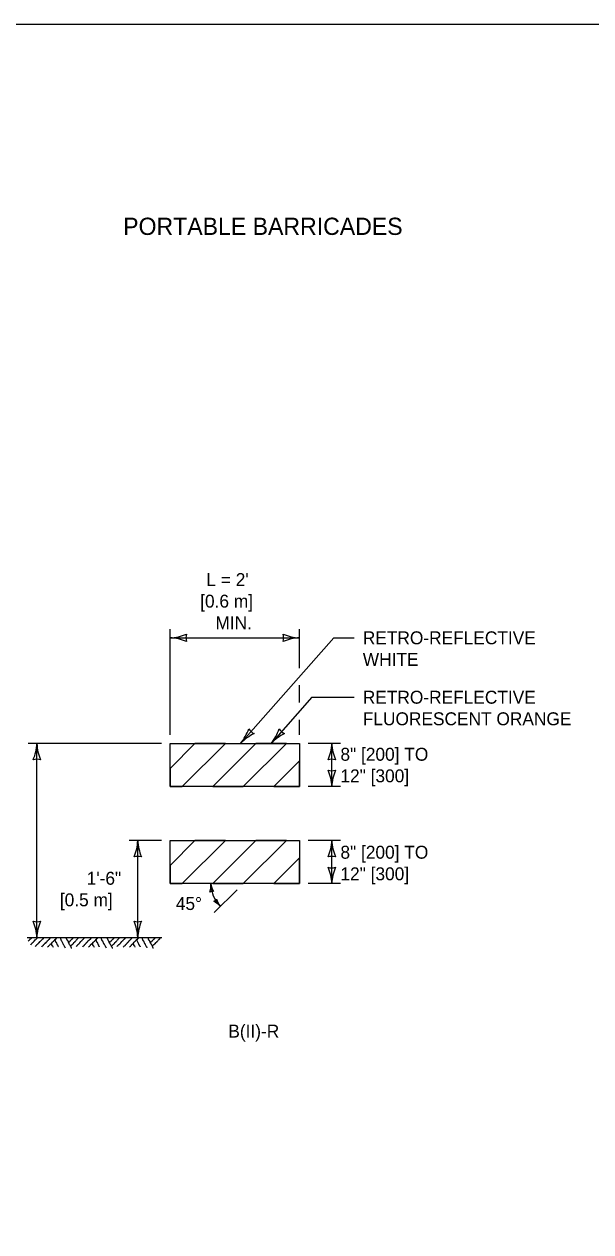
# Model space of a CAD drawing. Extents: x 49991.4 to 50021, y 49987.6 to 50011.4.
# Drawn here: x 50002.59 to 50005.22, y 49993.4 to 49999 of the extents above; entities that cross this region are included whole.
import ezdxf

# ---------------------------------------------------------------- set-up
doc = ezdxf.new("R2010")
doc.units = 0
for name, color, linetype in [('Level 1', 7, 'Continuous'), ('Level 2', 7, 'Continuous'), ('Level 3', 7, 'Continuous')]:
    doc.layers.add(name, color=color, linetype=linetype)

msp = doc.modelspace()

# ---------------------------------------------------------------- linework, layer by layer
at = {"layer": 'Level 1'}
for p, q in [((50003.2643, 49995.5483), (50003.3794, 49995.6636)), ((50003.3794, 49995.6636), (50003.2643, 49995.5483)), ((50003.321, 49995.4636), (50003.5207, 49995.6636)), ((50003.321, 49995.4636), (50003.5207, 49995.6636)), ((50003.4623, 49995.4636), (50003.662, 49995.6636)), ((50003.662, 49995.6636), (50003.4623, 49995.4636)), ((50003.6037, 49995.4636), (50003.8034, 49995.6636)), ((50003.6037, 49995.4636), (50003.8034, 49995.6636)), ((50003.7449, 49995.4636), (50003.8643, 49995.5832)), ((50003.8643, 49995.5832), (50003.7449, 49995.4636)), ((50003.2643, 49995.0983), (50003.3794, 49995.2136)), ((50003.3794, 49995.2136), (50003.2643, 49995.0983)), ((50003.321, 49995.0136), (50003.5207, 49995.2136)), ((50003.321, 49995.0136), (50003.5207, 49995.2136)), ((50003.4623, 49995.0136), (50003.662, 49995.2136)), ((50003.662, 49995.2136), (50003.4623, 49995.0136)), ((50003.6037, 49995.0136), (50003.8034, 49995.2136)), ((50003.6037, 49995.0136), (50003.8034, 49995.2136)), ((50003.7449, 49995.0136), (50003.8643, 49995.1332)), ((50003.8643, 49995.1332), (50003.7449, 49995.0136))]:
    msp.add_line(p, q, dxfattribs=at)
for points in [[(49999.3835, 49998.9992), (50016.7501, 49998.9992), (50016.7501, 49987.7988), (49999.3835, 49987.7988)], [(50003.2643, 49995.6636), (50003.8643, 49995.6636), (50003.8643, 49995.4636), (50003.2643, 49995.4636)], [(50003.2643, 49995.2136), (50003.8643, 49995.2136), (50003.8643, 49995.0136), (50003.2643, 49995.0136)]]:
    msp.add_lwpolyline(points, close=True, dxfattribs=at)
for points in [[(50003.5207, 49995.6636), (50003.3794, 49995.6636)], [(50003.8034, 49995.6636), (50003.662, 49995.6636)], [(50003.7449, 49995.4636), (50003.8643, 49995.4636), (50003.8643, 49995.5832)], [(50003.2643, 49995.5483), (50003.2643, 49995.4636)], [(50003.2643, 49995.4636), (50003.321, 49995.4636)], [(50003.4623, 49995.4636), (50003.6037, 49995.4636)], [(50003.5207, 49995.2136), (50003.3794, 49995.2136)], [(50003.8034, 49995.2136), (50003.662, 49995.2136)], [(50003.7449, 49995.0136), (50003.8643, 49995.0136), (50003.8643, 49995.1332)], [(50003.2643, 49995.0983), (50003.2643, 49995.0136)], [(50003.2643, 49995.0136), (50003.321, 49995.0136)], [(50003.4623, 49995.0136), (50003.6037, 49995.0136)], [(50002.6211, 49994.7636), (50002.6209, 49994.761), (50002.6177, 49994.7583), (50002.6176, 49994.7568), (50002.6161, 49994.757), (50002.6144, 49994.7542), (50002.613, 49994.7543), (50002.6128, 49994.7528), (50002.6097, 49994.7502), (50002.6096, 49994.7488), (50002.6081, 49994.7489), (50002.6065, 49994.7462)], [(50002.6513, 49994.7636), (50002.6424, 49994.7562), (50002.6423, 49994.7547), (50002.6409, 49994.7548), (50002.6392, 49994.7521), (50002.6362, 49994.7508), (50002.6343, 49994.7467), (50002.6313, 49994.7454), (50002.6312, 49994.744), (50002.628, 49994.7413), (50002.6279, 49994.7398), (50002.6264, 49994.7399), (50002.6247, 49994.7372), (50002.6233, 49994.7373), (50002.6231, 49994.7359), (50002.62, 49994.7332), (50002.6199, 49994.7317), (50002.6184, 49994.7319), (50002.6167, 49994.729)], [(50002.6784, 49994.7636), (50002.6722, 49994.7566), (50002.6721, 49994.7551), (50002.6706, 49994.7552), (50002.6689, 49994.7524), (50002.6642, 49994.7484), (50002.664, 49994.747), (50002.6625, 49994.7472), (50002.6608, 49994.7444), (50002.6579, 49994.7431), (50002.656, 49994.7389), (50002.653, 49994.7376), (50002.6529, 49994.7362), (50002.6496, 49994.7336), (50002.6495, 49994.7321), (50002.6481, 49994.7322), (50002.6464, 49994.7295), (50002.645, 49994.7296), (50002.6448, 49994.7281), (50002.6417, 49994.7255), (50002.6416, 49994.724), (50002.6401, 49994.7241), (50002.6383, 49994.7213)], [(50002.7099, 49994.7636), (50002.7017, 49994.7544), (50002.7016, 49994.7529), (50002.7001, 49994.7531), (50002.6983, 49994.7503), (50002.6937, 49994.7463), (50002.6936, 49994.7449), (50002.6921, 49994.745), (50002.6904, 49994.7421), (50002.6873, 49994.741), (50002.6855, 49994.7367), (50002.6825, 49994.7355), (50002.6824, 49994.7341), (50002.6792, 49994.7315), (50002.679, 49994.73), (50002.6776, 49994.7301), (50002.6759, 49994.7273), (50002.6744, 49994.7275), (50002.6743, 49994.726), (50002.6711, 49994.7233), (50002.671, 49994.7218), (50002.6696, 49994.722), (50002.6679, 49994.7192)], [(50002.7386, 49994.7636), (50002.7299, 49994.7538), (50002.7297, 49994.7524), (50002.7282, 49994.7525), (50002.7266, 49994.7497), (50002.7218, 49994.7457), (50002.7217, 49994.7443), (50002.7202, 49994.7444), (50002.7186, 49994.7416), (50002.7156, 49994.7404), (50002.7137, 49994.7361), (50002.7106, 49994.7349), (50002.7105, 49994.7335), (50002.7073, 49994.7309), (50002.7072, 49994.7294), (50002.7058, 49994.7295), (50002.704, 49994.7267), (50002.7027, 49994.7268), (50002.7025, 49994.7254), (50002.6993, 49994.7227), (50002.6992, 49994.7213), (50002.6978, 49994.7214), (50002.696, 49994.7186)], [(50002.713, 49994.7376), (50002.7165, 49994.7271), (50002.7194, 49994.7254), (50002.7218, 49994.7194)], [(50002.7295, 49994.7538), (50002.733, 49994.7433), (50002.7357, 49994.7416), (50002.7406, 49994.7294), (50002.742, 49994.7293), (50002.7433, 49994.7263), (50002.7431, 49994.7248), (50002.7458, 49994.7216), (50002.7461, 49994.7209)], [(50002.754, 49994.7636), (50002.7586, 49994.7502), (50002.7613, 49994.7485), (50002.7661, 49994.7363), (50002.7676, 49994.7362), (50002.7687, 49994.7333), (50002.7686, 49994.7318), (50002.7713, 49994.7287), (50002.7736, 49994.7226), (50002.7751, 49994.7224), (50002.7777, 49994.7161)], [(50002.7815, 49994.7636), (50002.7851, 49994.7527), (50002.7878, 49994.751), (50002.7927, 49994.7389), (50002.7942, 49994.7388), (50002.7954, 49994.7357), (50002.7952, 49994.7342), (50002.7979, 49994.7311), (50002.8004, 49994.725), (50002.8017, 49994.7249), (50002.8054, 49994.7158), (50002.8083, 49994.7156)], [(50002.8155, 49994.7636), (50002.8093, 49994.7565), (50002.8092, 49994.755), (50002.8077, 49994.7552), (50002.806, 49994.7524), (50002.8012, 49994.7484), (50002.801, 49994.747), (50002.7996, 49994.7471), (50002.7979, 49994.7443), (50002.7949, 49994.7431), (50002.7942, 49994.7415)], [(50002.841, 49994.7636), (50002.8309, 49994.7525), (50002.8308, 49994.751), (50002.8293, 49994.7511), (50002.8277, 49994.7483), (50002.8229, 49994.7444), (50002.8228, 49994.7429), (50002.8213, 49994.7431), (50002.8196, 49994.7403), (50002.8166, 49994.739), (50002.8147, 49994.7348), (50002.8116, 49994.7336), (50002.8115, 49994.7321), (50002.8084, 49994.7294), (50002.8082, 49994.728), (50002.8068, 49994.7281), (50002.8051, 49994.7254), (50002.8037, 49994.7255), (50002.8037, 49994.7251)], [(50002.8681, 49994.7636), (50002.8619, 49994.7566), (50002.8618, 49994.7551), (50002.8603, 49994.7552), (50002.8586, 49994.7524), (50002.8539, 49994.7484), (50002.8537, 49994.747), (50002.8522, 49994.7472), (50002.8505, 49994.7444), (50002.8476, 49994.7431), (50002.8457, 49994.7389), (50002.8427, 49994.7376), (50002.8426, 49994.7362), (50002.8393, 49994.7336), (50002.8392, 49994.7321), (50002.8378, 49994.7322), (50002.8361, 49994.7295), (50002.8347, 49994.7296), (50002.8345, 49994.7281), (50002.8314, 49994.7255), (50002.8313, 49994.724), (50002.8298, 49994.7241), (50002.828, 49994.7213)], [(50002.8996, 49994.7636), (50002.8914, 49994.7544), (50002.8913, 49994.7529), (50002.8898, 49994.7531), (50002.888, 49994.7503), (50002.8834, 49994.7463), (50002.8833, 49994.7449), (50002.8818, 49994.745), (50002.8801, 49994.7421), (50002.877, 49994.741), (50002.8752, 49994.7367), (50002.8722, 49994.7355), (50002.8721, 49994.7341), (50002.8689, 49994.7315), (50002.8687, 49994.73), (50002.8673, 49994.7301), (50002.8656, 49994.7273), (50002.8641, 49994.7275), (50002.864, 49994.726), (50002.8608, 49994.7233), (50002.8607, 49994.7218), (50002.8593, 49994.722), (50002.8576, 49994.7192)], [(50002.9283, 49994.7636), (50002.9196, 49994.7538), (50002.9194, 49994.7524), (50002.9179, 49994.7525), (50002.9163, 49994.7497), (50002.9115, 49994.7457), (50002.9114, 49994.7443), (50002.9099, 49994.7444), (50002.9083, 49994.7416), (50002.9053, 49994.7404), (50002.9034, 49994.7361), (50002.9003, 49994.7349), (50002.9002, 49994.7335), (50002.897, 49994.7309), (50002.8969, 49994.7294), (50002.8955, 49994.7295), (50002.8937, 49994.7267), (50002.8924, 49994.7268), (50002.8922, 49994.7254), (50002.889, 49994.7227), (50002.8889, 49994.7213), (50002.8875, 49994.7214), (50002.8857, 49994.7186)], [(50002.9027, 49994.7376), (50002.9062, 49994.7271), (50002.9091, 49994.7254), (50002.9115, 49994.7194)], [(50002.9192, 49994.7538), (50002.9227, 49994.7433), (50002.9254, 49994.7416), (50002.9303, 49994.7294), (50002.9317, 49994.7293), (50002.933, 49994.7263), (50002.9328, 49994.7248), (50002.9355, 49994.7216), (50002.9358, 49994.7209)], [(50002.9437, 49994.7636), (50002.9483, 49994.7502), (50002.951, 49994.7485), (50002.9558, 49994.7363), (50002.9573, 49994.7362), (50002.9584, 49994.7333), (50002.9583, 49994.7318), (50002.961, 49994.7287), (50002.9633, 49994.7226), (50002.9648, 49994.7224), (50002.9674, 49994.7161)], [(50002.9712, 49994.7636), (50002.9748, 49994.7527), (50002.9775, 49994.751), (50002.9824, 49994.7389), (50002.9839, 49994.7388), (50002.9851, 49994.7357), (50002.9849, 49994.7342), (50002.9876, 49994.7311), (50002.9901, 49994.725), (50002.9914, 49994.7249), (50002.9951, 49994.7158), (50002.998, 49994.7156)], [(50003.0052, 49994.7636), (50002.999, 49994.7565), (50002.9989, 49994.755), (50002.9974, 49994.7552), (50002.9957, 49994.7524), (50002.9909, 49994.7484), (50002.9907, 49994.747), (50002.9893, 49994.7471), (50002.9876, 49994.7443), (50002.9846, 49994.7431), (50002.9839, 49994.7415)], [(50003.0307, 49994.7636), (50003.0206, 49994.7525), (50003.0205, 49994.751), (50003.019, 49994.7511), (50003.0174, 49994.7483), (50003.0126, 49994.7444), (50003.0125, 49994.7429), (50003.011, 49994.7431), (50003.0093, 49994.7403), (50003.0063, 49994.739), (50003.0044, 49994.7348), (50003.0013, 49994.7336), (50003.0012, 49994.7321), (50002.9981, 49994.7294), (50002.9979, 49994.728), (50002.9965, 49994.7281), (50002.9948, 49994.7254), (50002.9934, 49994.7255), (50002.9934, 49994.7251)], [(50003.0578, 49994.7636), (50003.0516, 49994.7566), (50003.0515, 49994.7551), (50003.05, 49994.7552), (50003.0483, 49994.7524), (50003.0436, 49994.7484), (50003.0434, 49994.747), (50003.0419, 49994.7472), (50003.0402, 49994.7444), (50003.0373, 49994.7431), (50003.0354, 49994.7389), (50003.0324, 49994.7376), (50003.0323, 49994.7362), (50003.029, 49994.7336), (50003.0289, 49994.7321), (50003.0275, 49994.7322), (50003.0258, 49994.7295), (50003.0244, 49994.7296), (50003.0242, 49994.7281), (50003.0211, 49994.7255), (50003.021, 49994.724), (50003.0195, 49994.7241), (50003.0177, 49994.7213)], [(50003.0893, 49994.7636), (50003.0811, 49994.7544), (50003.081, 49994.7529), (50003.0795, 49994.7531), (50003.0777, 49994.7503), (50003.0731, 49994.7463), (50003.073, 49994.7449), (50003.0715, 49994.745), (50003.0698, 49994.7421), (50003.0667, 49994.741), (50003.0649, 49994.7367), (50003.0619, 49994.7355), (50003.0618, 49994.7341), (50003.0586, 49994.7315), (50003.0584, 49994.73), (50003.057, 49994.7301), (50003.0553, 49994.7273), (50003.0538, 49994.7275), (50003.0537, 49994.726), (50003.0505, 49994.7233), (50003.0504, 49994.7218), (50003.049, 49994.722), (50003.0473, 49994.7192)], [(50003.118, 49994.7636), (50003.1093, 49994.7538), (50003.1091, 49994.7524), (50003.1076, 49994.7525), (50003.106, 49994.7497), (50003.1012, 49994.7457), (50003.1011, 49994.7443), (50003.0996, 49994.7444), (50003.098, 49994.7416), (50003.095, 49994.7404), (50003.0931, 49994.7361), (50003.09, 49994.7349), (50003.0899, 49994.7335), (50003.0867, 49994.7309), (50003.0866, 49994.7294), (50003.0852, 49994.7295), (50003.0834, 49994.7267), (50003.0821, 49994.7268), (50003.0819, 49994.7254), (50003.0787, 49994.7227), (50003.0786, 49994.7213), (50003.0772, 49994.7214), (50003.0754, 49994.7186)], [(50003.0924, 49994.7376), (50003.0959, 49994.7271), (50003.0988, 49994.7254), (50003.1012, 49994.7194)], [(50003.1089, 49994.7538), (50003.1124, 49994.7433), (50003.1151, 49994.7416), (50003.12, 49994.7294), (50003.1214, 49994.7293), (50003.1227, 49994.7263), (50003.1225, 49994.7248), (50003.1252, 49994.7216), (50003.1255, 49994.7209)], [(50003.1334, 49994.7636), (50003.138, 49994.7502), (50003.1407, 49994.7485), (50003.1455, 49994.7363), (50003.147, 49994.7362), (50003.1481, 49994.7333), (50003.148, 49994.7318), (50003.1507, 49994.7287), (50003.153, 49994.7226), (50003.1545, 49994.7224), (50003.1571, 49994.7161)], [(50003.1609, 49994.7636), (50003.1645, 49994.7527), (50003.1672, 49994.751), (50003.1721, 49994.7389), (50003.1736, 49994.7388), (50003.1748, 49994.7357), (50003.1746, 49994.7342), (50003.1773, 49994.7311), (50003.1798, 49994.725), (50003.1811, 49994.7249), (50003.1848, 49994.7158), (50003.1877, 49994.7156)], [(50003.1949, 49994.7636), (50003.1887, 49994.7565), (50003.1886, 49994.755), (50003.1871, 49994.7552), (50003.1854, 49994.7524), (50003.1806, 49994.7484), (50003.1804, 49994.747), (50003.179, 49994.7471), (50003.1773, 49994.7443), (50003.1743, 49994.7431), (50003.1736, 49994.7415)], [(50003.2204, 49994.7636), (50003.2103, 49994.7525), (50003.2102, 49994.751), (50003.2087, 49994.7511), (50003.2071, 49994.7483), (50003.2023, 49994.7444), (50003.2022, 49994.7429), (50003.2007, 49994.7431), (50003.199, 49994.7403), (50003.196, 49994.739), (50003.1941, 49994.7348), (50003.191, 49994.7336), (50003.1909, 49994.7321), (50003.1878, 49994.7294), (50003.1876, 49994.728), (50003.1862, 49994.7281), (50003.1845, 49994.7254), (50003.1831, 49994.7255), (50003.1831, 49994.7251)]]:
    msp.add_lwpolyline(points, dxfattribs=at)
at = {"layer": 'Level 2'}
msp.add_line((50002.6022, 49994.7636), (50003.2264, 49994.7636), dxfattribs=at)
at = {"layer": 'Level 3'}
for p, q in [((50003.2643, 49995.7036), (50003.2643, 49996.1936)), ((50003.8643, 49996.0134), (50003.8643, 49996.1936)), ((50003.2643, 49996.1536), (50003.8643, 49996.1536)), ((50004.0231, 49996.1536), (50003.5914, 49995.6636)), ((50004.0231, 49996.1536), (50004.118, 49996.1536)), ((50003.8643, 49995.8531), (50003.8643, 49995.9334)), ((50003.9216, 49995.8781), (50003.7326, 49995.6636)), ((50003.9216, 49995.8781), (50004.118, 49995.8781)), ((50003.8643, 49995.7036), (50003.8643, 49995.7731)), ((50003.2243, 49995.6636), (50002.6064, 49995.6636)), ((50002.6464, 49994.7636), (50002.6464, 49995.6636)), ((50004.0543, 49995.6636), (50003.9043, 49995.6636)), ((50004.0143, 49995.4636), (50004.0143, 49995.6636)), ((50004.0543, 49995.4636), (50003.9043, 49995.4636)), ((50003.2243, 49995.2136), (50003.0743, 49995.2136)), ((50003.1143, 49994.7636), (50003.1143, 49995.2136)), ((50004.0543, 49995.2136), (50003.9043, 49995.2136)), ((50004.0143, 49995.0136), (50004.0143, 49995.2136)), ((50004.0543, 49995.0136), (50003.9043, 49995.0136)), ((50003.5754, 49994.9853), (50003.4692, 49994.8794))]:
    msp.add_line(p, q, dxfattribs=at)
for centre, radius, start, end in [((50003.2528, 49996.3863), 0.233, 272.8273, 292.0772), ((50003.2552, 49995.9314), 0.2223, 67.456, 87.6395), ((50003.3926, 49996.1536), 0.0548, 162.1388, 197.8612), ((50003.8735, 49996.3757), 0.2223, 247.456, 267.6395), ((50003.7361, 49996.1536), 0.0548, 342.1388, 17.8612), ((50003.8758, 49995.9208), 0.233, 92.8273, 112.0772), ((50003.4092, 49995.8088), 0.233, 321.4511, 340.7009), ((50003.6762, 49995.7598), 0.0548, 210.7626, 246.485), ((50003.5504, 49995.8087), 0.233, 321.454, 340.7038), ((50003.8174, 49995.7598), 0.0548, 210.7655, 246.4879), ((50003.7521, 49995.5099), 0.2223, 116.0798, 136.2633), ((50003.8933, 49995.5099), 0.2223, 116.0827, 136.2662), ((50002.4242, 49995.6727), 0.2223, 337.456, 357.6395), ((50002.8791, 49995.675), 0.233, 182.8273, 202.0772), ((50003.7922, 49995.6727), 0.2223, 337.456, 357.6395), ((50004.2471, 49995.675), 0.233, 182.8273, 202.0772), ((50002.6464, 49995.5353), 0.0548, 72.1388, 107.8612), ((50004.0143, 49995.5353), 0.0548, 72.1388, 107.8612), ((50004.0143, 49995.5918), 0.0548, 252.1388, 287.8612), ((50003.7816, 49995.4521), 0.233, 2.8273, 22.0772), ((50004.2365, 49995.4544), 0.2223, 157.456, 177.6395), ((50002.8922, 49995.2227), 0.2223, 337.456, 357.6395), ((50003.3471, 49995.225), 0.233, 182.8273, 202.0772), ((50003.7922, 49995.2227), 0.2223, 337.456, 357.6395), ((50004.2471, 49995.225), 0.233, 182.8273, 202.0772), ((50003.1143, 49995.0853), 0.0548, 72.1388, 107.8612), ((50004.0143, 49995.0853), 0.0548, 72.1388, 107.8612), ((50004.0143, 49995.1418), 0.0548, 252.1388, 287.8612), ((50003.7816, 49995.0021), 0.233, 2.8273, 22.0772), ((50004.2365, 49995.0044), 0.2223, 157.456, 177.6395), ((50003.3427, 49995.0077), 0.1112, 342.8326, 3.0161), ((50003.569, 49995.0302), 0.1165, 188.2039, 207.4537), ((50003.6037, 49995.0136), 0.15, 183.8545, 220.3605), ((50003.4597, 49994.9497), 0.0274, 77.5154, 113.2378), ((50003.4571, 49994.9574), 0.0274, 291.2236, 326.946), ((50003.4108, 49994.8298), 0.1165, 41.9121, 61.162), ((50003.5866, 49994.9741), 0.1112, 196.5408, 216.7243), ((50002.6464, 49994.8918), 0.0548, 252.1388, 287.8612), ((50002.4137, 49994.7521), 0.233, 2.8273, 22.0772), ((50002.8685, 49994.7544), 0.2223, 157.456, 177.6395), ((50003.1143, 49994.8918), 0.0548, 252.1388, 287.8612), ((50002.8816, 49994.7521), 0.233, 2.8273, 22.0772), ((50003.3365, 49994.7544), 0.2223, 157.456, 177.6395)]:
    msp.add_arc(centre, radius, start, end, dxfattribs=at)

# ---------------------------------------------------------------- texts
at = {"layer": 'Level 2'}
for s, height, p in [('PORTABLE BARRICADES', 0.08, (50003.0467, 49998.0218)), ("L = 2'", 0.06, (50003.4325, 49996.3936)), ('[0.6 m]', 0.06, (50003.4037, 49996.2936)), ('MIN.', 0.06, (50003.4745, 49996.1936)), ('RETRO-REFLECTIVE', 0.06, (50004.158, 49996.1236)), ('WHITE', 0.06, (50004.158, 49996.0236)), ('RETRO-REFLECTIVE', 0.06, (50004.158, 49995.8481)), ('FLUORESCENT ORANGE', 0.06, (50004.158, 49995.7481)), ('8" [200] TO', 0.06, (50004.0543, 49995.5836)), ('12" [300]', 0.06, (50004.0543, 49995.4836)), ('8" [200] TO', 0.06, (50004.0543, 49995.1293)), ('1\'-6"', 0.06, (50002.8774, 49995.0086)), ('12" [300]', 0.06, (50004.0543, 49995.0293)), ('[0.5 m]', 0.06, (50002.753, 49994.9086)), ('45°', 0.06, (50003.2908, 49994.8914)), ('B(II)-R', 0.06, (50003.5343, 49994.2997))]:
    msp.add_text(s, height=height, dxfattribs=at).set_placement(p)

doc.saveas('drawing.dxf')
